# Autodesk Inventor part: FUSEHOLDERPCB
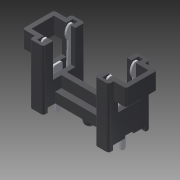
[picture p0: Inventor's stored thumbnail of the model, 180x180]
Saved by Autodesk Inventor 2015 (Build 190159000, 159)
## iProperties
Created: 2017-06
Part Number: FUSEHOLDERPCB
Material: Generic
Document SubType Name: Modeling
Designer: ThYnOx_2
Density: 1 g/cm^3
Appearance: Default
Author: ThYnOx_2
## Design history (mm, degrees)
sketch "Sketch1"
  geometry: L1 (-8.75, 4.625)-(8.75, 4.625); L2 (8.75, 4.625)-(8.75, -4.625); L3 (8.75, -4.625)-(-8.75, -4.625); L4 (-8.75, -4.625)-(-8.75, 4.625); L5 (-8.75, 4.625)-(8.75, -4.625); L6 (8.75, 4.625)-(-8.75, -4.625); L7 (-5.75, -4.625)-(-5.75, -2); L8 (-5.75, -2)-(5.75, -2); L9 (5.75, -2)-(5.75, -4.625); L10 (-5.75, 4.625)-(-5.75, 2); L11 (-5.75, 2)-(5.75, 2); L12 (5.75, 2)-(5.75, 4.625); 1 further point
  constraints: 24 end point, 5 perpendicular, 4 point on line, 2 midpoint, 2 parallel, 2 vertical, 1 horizontal
  dimensions: "d0" = 17.5 distance of L2.end L3.end; "d1" = 9.25 distance of L1.end L2.end; "d2" = 3 distance between parallel lines of L4 L7; "d3" = 3 distance between parallel lines of L2 L9; "d5" = 2.625 distance between parallel lines of L3 L8; "d6" = 2.625 distance between parallel lines of L11 L1
extrude "Extrusion1" new body sketch "Sketch1" distance "d7" = 13.25; taper "d8" = 0 deg
sketch "Sketch2"
  geometry: L1 (-8.75, 4.625)-(-8.75, -4.625) reference; L2 (8.75, -4.625)-(8.75, 4.625) reference; L3 (11.5, 3.5)-(11.5, -3.5); L4 (-11.5, -3.5)-(-11.5, 3.5); L5 (-11.5, 3.5)-(11.5, -3.5); L6 (11.5, 3.5)-(-11.5, -3.5); L7 (-11.5, 3.5)-(-8.75, 3.5); L8 (8.75, 3.5)-(11.5, 3.5); L9 (11.5, -3.5)-(8.75, -3.5); L10 (-8.75, -3.5)-(-11.5, -3.5); 1 further point
  constraints: 16 end point, 5 parallel, 4 point on line, 2 horizontal, 2 midpoint, 2 perpendicular
  dimensions: "d9" = 23 distance of L3.end L4.start; "d10" = 7 distance of L3.start L3.end
extrude "Extrusion2" join sketch "Sketch2" distance "d11" = 3.7; taper "d12" = 0 deg
sketch "Sketch3"
  geometry: L1 (-10.5, 2.5)-(10.5, 2.5); L2 (10.5, 2.5)-(10.5, -2.5); L3 (10.5, -2.5)-(-10.5, -2.5); L4 (-10.5, -2.5)-(-10.5, 2.5); L5 (-10.5, 2.5)-(10.5, -2.5); L6 (10.5, 2.5)-(-10.5, -2.5); 1 further point
  constraints: 12 end point, 2 midpoint, 2 parallel, 1 horizontal, 1 perpendicular
  dimensions: "d13" = 21 distance of L2.end L3.end; "d14" = 5 distance of L1.end L2.end
extrude "Extrusion3" cut sketch "Sketch3" distance "d15" = 10; taper "d16" = 0 deg
sketch "Sketch4"
  geometry: L1 (-8.75, -4.625)-(-8.75, 4.625) reference; L2 (8.75, -4.625)-(5.75, -4.625) reference; L3 (8.75, -3.625)-(-8.75, -3.625); L4 (-8.75, -3.625)-(-8.75, 3.625); L5 (-8.75, 3.625)-(8.75, 3.625); L6 (8.75, 3.625)-(8.75, -3.625); L7 (8.75, -3.625)-(-8.75, 3.625); L8 (-8.75, -3.625)-(8.75, 3.625); 1 further point
  constraints: 12 end point, 2 midpoint, 2 parallel, 1 horizontal, 1 perpendicular, 1 point on line
  dimensions: "d17" = 1 distance between parallel lines of L2 L3
extrude "Extrusion4" cut sketch "Sketch4" distance "d18" = 1; taper "d19" = 0 deg
sketch "Sketch5"
  geometry: C1 r 1.2 at (0, 0); 1 further point
  constraints: 1 centre point, 1 coincident
  dimensions: "d20" = 1.2 radius of C1
extrude "Extrusion5" join sketch "Sketch5" distance "d21" = 2.2; taper "d22" = 0 deg
sketch "Sketch6"
  geometry: L1 (8.75, 2.5)-(8.75, -2.5) reference; L2 (-8.75, 0.6)-(8.75, 0.6); L3 (8.75, 0.6)-(8.75, -0.6); L4 (8.75, -0.6)-(-8.75, -0.6); L5 (-8.75, -0.6)-(-8.75, 0.6); L6 (-8.75, 0.6)-(8.75, -0.6); L7 (8.75, 0.6)-(-8.75, -0.6); 1 further point
  constraints: 12 end point, 2 midpoint, 2 parallel, 1 horizontal, 1 perpendicular, 1 point on line
  dimensions: "d23" = 1.2 distance of L2.end L3.end
extrude "Extrusion6" join sketch "Sketch6" distance "d24" = 2.5; taper "d25" = 0 deg
sketch "Sketch7"
  geometry: L1 (-8.75, 2.5)-(-5.75, 2.5); L2 (-5.75, 2.5)-(-5.75, -2.5); L3 (-5.75, -2.5)-(-8.75, -2.5); L4 (-8.75, -2.5)-(-8.75, 2.5); L5 (5.75, 2.5)-(8.75, 2.5); L6 (8.75, 2.5)-(8.75, -2.5); L7 (8.75, -2.5)-(5.75, -2.5); L8 (5.75, -2.5)-(5.75, 2.5); 1 further point
  constraints: 16 end point, 4 parallel, 2 horizontal, 2 perpendicular
extrude "Extrusion7" join sketch "Sketch7" distance "d26" = 2.5; taper "d27" = 0 deg
sketch "Sketch8"
  geometry: L1 (8.75, -2.5)-(5.75, -2.5) reference; L2 (-5.75, -2.5)-(-8.75, -2.5) reference; L3 (-8.75, 2.5)-(-7.75, 2.5); L4 (-7.75, 2.5)-(-7.75, -2.5); L5 (-7.75, -2.5)-(-8.75, -2.5); L6 (-8.75, -2.5)-(-8.75, 2.5); L7 (8.75, 2.5)-(7.75, 2.5); L8 (7.75, 2.5)-(7.75, -2.5); L9 (7.75, -2.5)-(8.75, -2.5); L10 (8.75, -2.5)-(8.75, 2.5); 1 further point
  constraints: 16 end point, 4 parallel, 2 horizontal, 2 perpendicular, 2 point on line
  dimensions: "d28" = 1 distance of L4.end L5.end; "d29" = 1 distance of L9.end L8.end
extrude "Extrusion8" join sketch "Sketch8" distance "d30" = 1; taper "d31" = 0 deg
sketch "Sketch9"
  geometry: L1 (-8.75, -3.625)-(-8.75, 3.625) reference; L2 (8.75, 3.625)-(8.75, -3.625) reference; L3 (-8.75, -1)-(-8.75, 1); L4 (8.75, 1)-(8.75, -1); L5 (8.75, -1)-(-8.75, 1); L6 (-8.75, -1)-(8.75, 1); L7 (6.75, -1)-(6.75, 1); L8 (-6.75, -1)-(-6.75, 1); L9 (8.75, -1)-(6.75, -1); L10 (6.75, 1)-(8.75, 1); L11 (0.663, -1)-(-0.663, -1); L12 (-6.75, -1)-(-8.75, -1); L13 (-8.75, 1)-(-6.75, 1); L14 (-0.663, 1)-(0.663, 1); A1 r 1.2 centre (0, 0) between (0.663, -1) and (0.663, 1) reference
  constraints: 24 end point, 10 parallel, 9 perpendicular, 4 point on circle, 3 horizontal, 2 midpoint, 1 point on line
  dimensions: "d32" = 2 distance of L3.start L3.end; "d33" = 2 distance between parallel lines of L2 L7; "d34" = 2 distance between parallel lines of L8 L1
extrude "Extrusion9" cut sketch "Sketch9" distance "d35" = 0.5; taper "d36" = 0 deg
sketch "Sketch10"
  geometry: L1 (6.75, 1)-(8.75, 1) reference; L2 (6.75, -1)-(7.75, -1); L3 (7.75, -1)-(7.75, 1); L4 (7.75, 1)-(6.75, 1); L5 (6.75, 1)-(6.75, -1); L6 (8.75, 1)-(8.75, -1) reference; 1 further point
  constraints: 8 end point, 2 parallel, 1 horizontal, 1 midpoint, 1 perpendicular
  dimensions: "d40" = 1 distance between parallel lines of L6 L3
extrude "Extrusion10" cut sketch "Sketch10" stored distance "d38" = 0.5; taper "d39" = 0 deg
sketch "Sketch11"
  geometry: L1 (-8.75, 1)-(-6.75, 1) reference; L2 (-6.75, -1)-(-7.75, -1); L3 (-7.75, -1)-(-7.75, 1); L4 (-7.75, 1)-(-6.75, 1); L5 (-6.75, 1)-(-6.75, -1); 1 further point
  constraints: 8 end point, 2 parallel, 1 horizontal, 1 midpoint, 1 perpendicular
  dimensions: "d41" = 1 distance of L3.end L4.end (derived)
extrude "Extrusion11" cut sketch "Sketch11" stored distance "d42" = 0.5; taper "d43" = 0 deg
sketch "Sketch12"
  geometry: L1 (-5.75, 2.5)-(-5.75, 4.625) reference; L2 (-5.75, 4.625)-(-8.75, 4.625) reference; L3 (-8.75, 4.625)-(-8.75, 3.5) reference; L4 (-8.75, -4.625)-(-5.75, -4.625) reference; L5 (-7.75, 4)-(-6.75, 4); L6 (-6.75, 4)-(-6.75, -4); L7 (-6.75, -4)-(-7.75, -4); L8 (-7.75, -4)-(-7.75, 4); 1 further point
  constraints: 8 end point, 2 parallel, 1 horizontal, 1 perpendicular
  dimensions: "d44" = 1 distance between parallel lines of L1 L6; "d45" = 1 distance between parallel lines of L3 L8; "d46" = 0.625 distance between parallel lines of L5 L2; "d47" = 0.625 distance between parallel lines of L4 L7
extrude "Extrusion12" cut sketch "Sketch12" distance "d48" = 11; taper "d49" = 0 deg
workplane "Work Plane1"
sketch "Sketch13"
  geometry: L1 (11.75, 4.5)-(3.65, 4.5); L2 (3.65, -2.5)-(11.75, -2.5); L3 (12.25, -3)-(1.25, -3) reference; L4 (1.65, 0)-(0.05, 0); L5 (0.05, 2)-(1.65, 2); L6 (-0.35, 1.5)-(-2.95, 1.5); L7 (-3.35, 1.1)-(-3.35, 0.9); L8 (-2.95, 0.5)-(-0.35, 0.5); L9 (1.65, 2.5)-(1.65, 2); L10 (1.65, 0)-(1.65, -0.5); L11 (-0.35, 0.4)-(-0.35, 0.5); L12 (-0.35, 1.5)-(-0.35, 1.6); L13 (3.057, -0.5)-(3.057, -0.5); L14 (3.057, 2.5)-(3.057, 2.5); L15 (3.557, 2)-(5.657, 2); L16 (6.057, 1.6)-(6.057, 0.4); L17 (5.657, 0)-(3.557, 0); L18 (9.25, 3.3)-(3.628, 3.092); L19 (12.25, -1.5)-(12.25, -2); L20 (12.25, 4)-(12.25, 3.5); L21 (9.25, -1.3)-(3.65, -1.093); A1 r 2 centre (3.65, 2.5) between (3.65, 4.5) and (1.65, 2.5); A2 r 2 centre (3.65, -0.5) between (1.65, -0.5) and (3.65, -2.5); A3 r 0.593 centre (3.65, -0.5) between (3.057, -0.5) and (3.65, -1.093); A4 r 0.593 centre (3.65, 2.5) between (3.628, 3.092) and (3.057, 2.5); A5 r 0.5 centre (3.557, 2.5) between (3.057, 2.5) and (3.557, 2); A6 r 0.5 centre (3.557, -0.5) between (3.557, 0) and (3.057, -0.5); A7 r 2.118 centre (10.651, 4.889) between (9.25, 3.3) and (12.25, 3.5); A8 r 2.118 centre (10.651, -2.889) between (12.25, -1.5) and (9.25, -1.3); A9 r 0.5 centre (11.75, 4) between (12.25, 4) and (11.75, 4.5); A10 r 0.5 centre (11.75, -2) between (11.75, -2.5) and (12.25, -2); A11 r 0.4 centre (5.657, 0.4) between (5.657, 0) and (6.057, 0.4); A12 r 0.4 centre (5.657, 1.6) between (6.057, 1.6) and (5.657, 2); A13 r 0.4 centre (0.05, 1.6) between (0.05, 2) and (-0.35, 1.6); A14 r 0.4 centre (0.05, 0.4) between (-0.35, 0.4) and (0.05, 0); A15 r 0.4 centre (-2.95, 1.1) between (-2.95, 1.5) and (-3.35, 1.1); A16 r 0.4 centre (-2.95, 0.9) between (-3.35, 0.9) and (-2.95, 0.5); 4 further points
  constraints: 40 end point, 32 point on circle, 25 tangent, 16 centre point, 8 equal radius, 8 point on line, 6 perpendicular, 4 horizontal, 4 parallel, 1 vertical
  dimensions: "d56" = 2 distance of point (-0.35, 0) point (-0.35, 2); "d59" = 1 distance of point (-3.35, 0.5) point (-3.35, 1.5); "d60" = 0.5 distance between parallel lines of L4 L8; "d65" = 0.5 radius of A5; "d70" = 1.2 distance from line of L1 L18.start; "d72" = 0.4 radius of A11
extrude "Extrusion13" new body sketch "Sketch13" stored distance "d73" = 0.4; taper "d74" = 0 deg
mirror "Mirror1"
fillet "Fillet1" dims "d75" = 0.5
sketch "Sketch14"
  geometry: L1 (6.25, -4.625)-(8.25, -4.625) reference; L2 (8.75, -4.125)-(8.75, -3.5) reference; L3 (8.25, 4.625)-(6.25, 4.625) reference; L4 (5.75, -2.5)-(5.75, -4.125) reference; L5 (6.75, 4)-(7.75, 4); L6 (7.75, 4)-(7.75, -4); L7 (7.75, -4)-(6.75, -4); L8 (6.75, -4)-(6.75, 4); 1 further point
  constraints: 8 end point, 2 parallel, 1 horizontal, 1 perpendicular
  dimensions: "d76" = 0.625 distance between parallel lines of L3 L5; "d77" = 0.625 distance between parallel lines of L1 L7; "d78" = 1 distance between parallel lines of L4 L8; "d79" = 1 distance between parallel lines of L2 L6
extrude "Extrusion14" cut sketch "Sketch14" distance "d80" = 11; taper "d81" = 0 deg
fillet "Fillet2" dims "d82" = 1
sketch "Sketch15"
  geometry: L1 (-1.5, 0.25)-(1.5, 0.25); L2 (1.5, 0.25)-(1.5, -0.25); L3 (1.5, -0.25)-(-1.5, -0.25); L4 (-1.5, -0.25)-(-1.5, 0.25); L5 (-1.5, 0.25)-(1.5, -0.25); L6 (1.5, 0.25)-(-1.5, -0.25); C1 r 0.2 at (0, 0) reference
  constraints: 12 end point, 2 midpoint, 2 parallel, 1 horizontal, 1 perpendicular
  dimensions: "d83" = 3 distance of L2.end L3.end; "d84" = 0.5 distance of L1.end L2.end
extrude "Extrusion15" cut sketch "Sketch15" distance "d85" = 1; taper "d86" = 0 deg
body "Solid1"
body "Solid2"
feature "Pattern of Solid2:1"
body "Solid3"
other parameters: "d50" = 0.5, "d54" = 10.6
